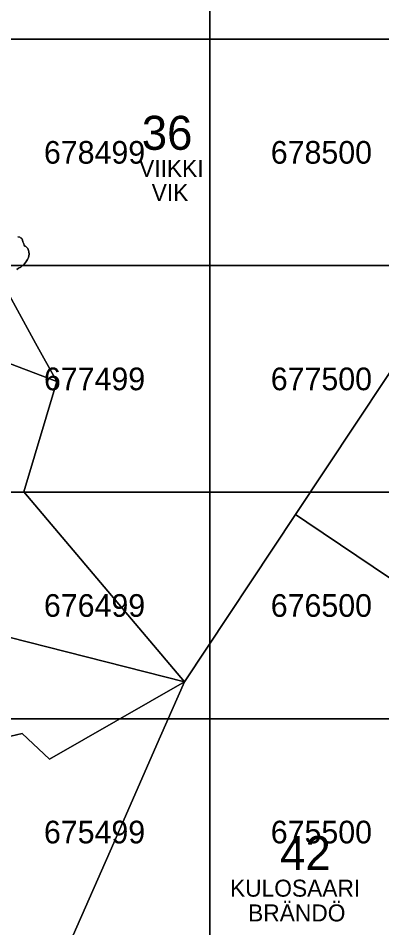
# Model space of a CAD drawing. Extents: x 25485000 to 25520000, y 6656775 to 6690000.
# Drawn here: x 25499155 to 25500758, y 6675077 to 6679092 of the extents above; entities that cross this region are included whole.
import ezdxf

# ---------------------------------------------------------------- set-up
doc = ezdxf.new("R2010")
doc.units = 0
doc.layers.add('Level 63', color=7, linetype='Continuous')

msp = doc.modelspace()

# ---------------------------------------------------------------- linework, layer by layer
at = {"layer": 'Level 63'}
for points in [[(25499000, 6679000), (25500000, 6679000), (25500000, 6680000), (25499000, 6680000)], [(25500000, 6679000), (25501000, 6679000), (25501000, 6680000), (25500000, 6680000)], [(25499000, 6678000), (25500000, 6678000), (25500000, 6679000), (25499000, 6679000)], [(25500000, 6678000), (25501000, 6678000), (25501000, 6679000), (25500000, 6679000)], [(25499000, 6677000), (25500000, 6677000), (25500000, 6678000), (25499000, 6678000)], [(25500000, 6677000), (25501000, 6677000), (25501000, 6678000), (25500000, 6678000)], [(25499000, 6676000), (25500000, 6676000), (25500000, 6677000), (25499000, 6677000)], [(25500000, 6676000), (25501000, 6676000), (25501000, 6677000), (25500000, 6677000)], [(25499000, 6675000), (25500000, 6675000), (25500000, 6676000), (25499000, 6676000)], [(25500000, 6675000), (25501000, 6675000), (25501000, 6676000), (25500000, 6676000)]]:
    msp.add_lwpolyline(points, close=True, dxfattribs=at)
for points in [[(25499148.5, 6677983.6), (25499156.8, 6677988.8), (25499166.1, 6677993.8), (25499180.9, 6678005.8), (25499188.8, 6678015.4), (25499190.1, 6678018.2), (25499192.6, 6678022.7), (25499196.3, 6678026.7), (25499200.4, 6678035.4), (25499203.3, 6678050.3), (25499202.2, 6678060.6), (25499201.1, 6678067.5), (25499197.1, 6678075.1), (25499189.2, 6678085.1), (25499184.9, 6678085.6), (25499181, 6678089.6), (25499179.4, 6678095.8), (25499175.7, 6678105.5), (25499174.2, 6678112.6), (25499170.7, 6678119.8), (25499169.5, 6678121.7), (25499167.5, 6678120.9), (25499165.4, 6678122.8), (25499161.5, 6678126.3), (25499152.8, 6678127.3)], [(25499152.8, 6678127.3), (25499161.5, 6678126.3), (25499165.4, 6678122.8), (25499167.5, 6678120.9), (25499169.5, 6678121.7), (25499170.7, 6678119.8), (25499174.2, 6678112.6), (25499175.7, 6678105.5), (25499179.4, 6678095.8), (25499181, 6678089.6), (25499184.9, 6678085.6), (25499189.2, 6678085.1), (25499197.1, 6678075.1), (25499201.1, 6678067.5), (25499202.2, 6678060.6), (25499203.3, 6678050.3), (25499200.4, 6678035.4), (25499196.3, 6678026.7), (25499192.6, 6678022.7), (25499190.1, 6678018.2), (25499188.8, 6678015.4), (25499180.9, 6678005.8), (25499166.1, 6677993.8), (25499156.8, 6677988.8), (25499148.5, 6677983.6)], [(25499116.9, 6677867.7), (25499231.7, 6677658.5), (25499324.7, 6677489.2), (25499179.8, 6677001.7), (25499887.6, 6676162.5), (25500377.3, 6676901.5), (25501042.6, 6677905.5)], [(25501042.6, 6677905.5), (25500377.3, 6676901.5), (25500427.3, 6676867.8), (25501089.3, 6676421.3)], [(25499053.2, 6677591.3), (25499324.7, 6677489.2), (25499231.7, 6677658.5), (25499116.9, 6677867.7)], [(25498592.6, 6676492.8), (25499887.6, 6676162.5), (25499179.8, 6677001.7), (25499324.7, 6677489.2), (25499053.2, 6677591.3)], [(25501089.3, 6676421.3), (25500427.3, 6676867.8), (25500377.3, 6676901.5), (25499887.6, 6676162.5), (25499782.6, 6675923.4), (25499559.7, 6675415.6), (25499304.6, 6674834.5), (25499290.4, 6674802.1), (25499383.4, 6674743.1), (25499528.4, 6674650.9), (25499804.3, 6674475.3), (25499816, 6674467.8), (25500077.8, 6674301.6), (25500206, 6674219.8), (25500113.5, 6673489.1), (25501011.9, 6673933.9)], [(25499122.2, 6675923.5), (25499172.3, 6675934.6), (25499292.4, 6675821.8), (25499887.6, 6676162.5), (25498592.6, 6676492.8)], [(25499304.6, 6674834.5), (25499559.7, 6675415.6), (25499782.6, 6675923.4), (25499887.6, 6676162.5), (25499292.4, 6675821.8), (25499172.3, 6675934.6), (25499122.2, 6675923.5)]]:
    msp.add_lwpolyline(points, dxfattribs=at)

# ---------------------------------------------------------------- texts
for s, height, p in [('36', 150, (25499700, 6678511.2)), ('678499', 100, (25499268.5, 6678450)), ('678500', 100, (25500268.5, 6678450)), ('VIIKKI', 75, (25499688.1, 6678391.7)), ('VIK', 75, (25499743.5, 6678285.2)), ('677499', 100, (25499268.5, 6677450)), ('677500', 100, (25500268.5, 6677450)), ('676499', 100, (25499268.5, 6676450)), ('676500', 100, (25500268.5, 6676450)), ('675499', 100, (25499268.5, 6675450)), ('675500', 100, (25500268.5, 6675450)), ('42', 150, (25500309.6, 6675332.4)), ('KULOSAARI', 75, (25500088.7, 6675214.8)), ('BRÄNDÖ', 75, (25500168.5, 6675105.6))]:
    msp.add_text(s, height=height, dxfattribs=at).set_placement(p)

doc.saveas('drawing.dxf')
